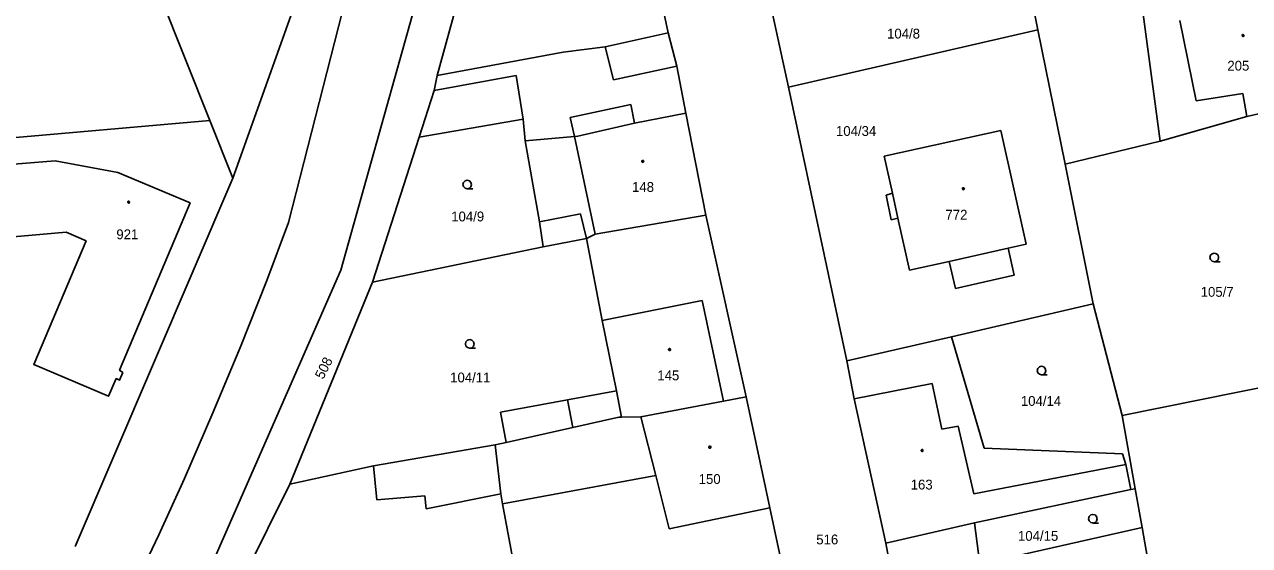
# Model space of a CAD drawing. Extents: x -757994 to -755874, y -1047691 to -1046119.
# Drawn here: x -756803.8 to -756698, y -1047019.3 to -1046974.3 of the extents above; entities that cross this region are included whole.
import ezdxf

# ---------------------------------------------------------------- set-up
doc = ezdxf.new("R2010")
doc.units = 0
doc.layers.add('katastrální mapa', color=7, linetype='Continuous')

msp = doc.modelspace()

# ---------------------------------------------------------------- linework, layer by layer
at = {"layer": 'katastrální mapa'}
for p, q in [((-756780.99, -1046991.44), (-756764.8, -1046928)), ((-756761.62, -1046942.65), (-756776.48, -1046995.54)), ((-756795.15, -1046964.07), (-756787.79, -1046982.63)), ((-756748.23, -1046975.07), (-756750.24, -1046965.33)), ((-756718.11, -1046965.95), (-756716.32, -1046974.79)), ((-756739.82, -1046970.56), (-756737.85, -1046979.76)), ((-756779.83, -1046970.85), (-756785.81, -1046987.62)), ((-756766.02, -1046970.94), (-756768.15, -1046978.75)), ((-756707.62, -1046970.57), (-756705.75, -1046984.42)), ((-756737.85, -1046979.76), (-756716.32, -1046974.79)), ((-756716.32, -1046974.79), (-756713.97, -1046986.4)), ((-756702.65, -1046980.93), (-756704.07, -1046974)), ((-756748.23, -1046975.07), (-756753.66, -1046976.28)), ((-756747.48, -1046977.94), (-756748.23, -1046975.07)), ((-756757.28, -1046976.74), (-756768.15, -1046978.75)), ((-756753.66, -1046976.28), (-756757.28, -1046976.74)), ((-756753.66, -1046976.28), (-756752.95, -1046979.13)), ((-756752.95, -1046979.13), (-756747.48, -1046977.94)), ((-756746.7, -1046982), (-756747.48, -1046977.94)), ((-756768.15, -1046978.75), (-756768.41, -1046980.03)), ((-756768.41, -1046980.03), (-756761.35, -1046978.75)), ((-756761.35, -1046978.75), (-756760.74, -1046982.5)), ((-756768.41, -1046980.03), (-756769.71, -1046984.06)), ((-756737.85, -1046979.76), (-756732.81, -1047003.38)), ((-756698.61, -1046980.3), (-756702.65, -1046980.93)), ((-756698.29, -1046982.28), (-756698.61, -1046980.3)), ((-756698.29, -1046982.28), (-756692.58, -1046980.95)), ((-756751.44, -1046981.26), (-756756.67, -1046982.36)), ((-756751.12, -1046982.87), (-756751.44, -1046981.26)), ((-756746.7, -1046982), (-756751.12, -1046982.87)), ((-756744.98, -1046990.79), (-756746.7, -1046982)), ((-756787.79, -1046982.63), (-756815.18, -1046985.04)), ((-756787.79, -1046982.63), (-756785.81, -1046987.62)), ((-756769.71, -1046984.06), (-756760.74, -1046982.5)), ((-756760.74, -1046982.5), (-756760.57, -1046984.38)), ((-756756.67, -1046982.36), (-756756.32, -1046984.02)), ((-756751.12, -1046982.87), (-756756.01, -1046983.99)), ((-756705.75, -1046984.42), (-756698.29, -1046982.28)), ((-756769.71, -1046984.06), (-756773.74, -1046996.58)), ((-756756.32, -1046984.02), (-756760.57, -1046984.38)), ((-756756.01, -1046983.99), (-756756.32, -1046984.02)), ((-756756.32, -1046984.02), (-756754.53, -1046992.45)), ((-756719.51, -1046983.48), (-756729.59, -1046985.71)), ((-756717.32, -1046993.32), (-756719.51, -1046983.48)), ((-756760.57, -1046984.38), (-756759.32, -1046991.39)), ((-756713.97, -1046986.4), (-756705.75, -1046984.42)), ((-756729.59, -1046985.71), (-756728.87, -1046988.91)), ((-756713.97, -1046986.4), (-756711.55, -1046998.45)), ((-756799.4, -1047019.41), (-756785.81, -1046987.62)), ((-756728.87, -1046988.91), (-756729.42, -1046989.07)), ((-756729.42, -1046989.07), (-756728.98, -1046991.2)), ((-756728.87, -1046988.91), (-756728.39, -1046991.07)), ((-756755.79, -1046990.69), (-756759.32, -1046991.39)), ((-756759.32, -1046991.39), (-756759.01, -1046993.53)), ((-756755.28, -1046992.81), (-756755.79, -1046990.69)), ((-756744.98, -1046990.79), (-756754.53, -1046992.45)), ((-756741.49, -1047006.49), (-756744.98, -1046990.79)), ((-756728.98, -1046991.2), (-756728.39, -1046991.07)), ((-756728.39, -1046991.07), (-756727.39, -1046995.56)), ((-756754.53, -1046992.45), (-756755.28, -1046992.81)), ((-756759.01, -1046993.53), (-756773.74, -1046996.58)), ((-756759.01, -1046993.53), (-756755.28, -1046992.81)), ((-756755.28, -1046992.81), (-756753.91, -1046999.9)), ((-756723.96, -1046994.8), (-756718.88, -1046993.66)), ((-756718.88, -1046993.66), (-756717.32, -1046993.32)), ((-756718.37, -1046995.98), (-756718.88, -1046993.66)), ((-756727.39, -1046995.56), (-756723.96, -1046994.8)), ((-756723.96, -1046994.8), (-756723.43, -1046997.14)), ((-756776.48, -1046995.54), (-756787.52, -1047020.76)), ((-756773.74, -1046996.58), (-756780.89, -1047014.02)), ((-756723.43, -1046997.14), (-756718.37, -1046995.98)), ((-756745.28, -1046998.17), (-756753.91, -1046999.9)), ((-756743.45, -1047006.86), (-756745.28, -1046998.17)), ((-756723.78, -1047001.31), (-756711.55, -1046998.45)), ((-756711.55, -1046998.45), (-756709.03, -1047008.1)), ((-756753.91, -1046999.9), (-756752.69, -1047005.97)), ((-756732.81, -1047003.38), (-756723.78, -1047001.31)), ((-756723.78, -1047001.31), (-756720.96, -1047010.91)), ((-756732.81, -1047003.38), (-756732.18, -1047006.66)), ((-756709.03, -1047008.1), (-756687.9, -1047003.85)), ((-756732.18, -1047006.66), (-756725.45, -1047005.34)), ((-756725.45, -1047005.34), (-756724.6, -1047009.29)), ((-756752.69, -1047005.97), (-756756.9, -1047006.74)), ((-756752.69, -1047005.97), (-756752.24, -1047008.24)), ((-756741.49, -1047006.49), (-756743.45, -1047006.86)), ((-756739.44, -1047016.08), (-756741.49, -1047006.49)), ((-756756.9, -1047006.74), (-756762.7, -1047007.8)), ((-756756.45, -1047009.13), (-756756.9, -1047006.74)), ((-756743.45, -1047006.86), (-756750.57, -1047008.22)), ((-756732.18, -1047006.66), (-756729.44, -1047019.12)), ((-756762.7, -1047007.8), (-756762.21, -1047010.42)), ((-756752.47, -1047008.24), (-756756.45, -1047009.13)), ((-756752.24, -1047008.24), (-756752.47, -1047008.24)), ((-756750.57, -1047008.22), (-756752.24, -1047008.24)), ((-756750.57, -1047008.22), (-756749.29, -1047013.29)), ((-756707.91, -1047014.42), (-756709.03, -1047008.1)), ((-756756.45, -1047009.13), (-756762.21, -1047010.42)), ((-756724.6, -1047009.29), (-756723.19, -1047009.01)), ((-756723.19, -1047009.01), (-756721.83, -1047014.85)), ((-756763.15, -1047010.63), (-756773.65, -1047012.46)), ((-756762.21, -1047010.42), (-756763.15, -1047010.63)), ((-756762.66, -1047014.85), (-756763.15, -1047010.63)), ((-756720.96, -1047010.91), (-756709.01, -1047011.4)), ((-756709.01, -1047011.4), (-756708.71, -1047012.33)), ((-756773.65, -1047012.46), (-756780.89, -1047014.02)), ((-756773.37, -1047015.39), (-756773.65, -1047012.46)), ((-756721.83, -1047014.85), (-756708.71, -1047012.33)), ((-756708.71, -1047012.33), (-756708.29, -1047014.5)), ((-756749.29, -1047013.29), (-756762.53, -1047015.73)), ((-756749.29, -1047013.29), (-756748.13, -1047017.89)), ((-756780.89, -1047014.02), (-756790.18, -1047032.81)), ((-756762.66, -1047014.85), (-756769.1, -1047016.15)), ((-756762.53, -1047015.73), (-756762.66, -1047014.85)), ((-756721.78, -1047017.37), (-756708.29, -1047014.5)), ((-756708.29, -1047014.5), (-756707.91, -1047014.42)), ((-756707.32, -1047017.76), (-756707.91, -1047014.42)), ((-756769.23, -1047015.03), (-756773.37, -1047015.39)), ((-756769.1, -1047016.15), (-756769.23, -1047015.03)), ((-756761.2, -1047022.76), (-756762.53, -1047015.73)), ((-756739.44, -1047016.08), (-756748.13, -1047017.89)), ((-756738.2, -1047021.87), (-756739.44, -1047016.08)), ((-756729.44, -1047019.12), (-756721.78, -1047017.37)), ((-756721.32, -1047020.94), (-756721.78, -1047017.37)), ((-756721.32, -1047020.94), (-756707.32, -1047017.76)), ((-756705.85, -1047026.09), (-756707.32, -1047017.76)), ((-756729.44, -1047019.12), (-756728.9, -1047021.94))]:
    msp.add_line(p, q, dxfattribs=at)
for points in [[(-756698.61, -1046975.21), (-756698.56, -1046975.22), (-756698.53, -1046975.26), (-756698.52, -1046975.29), (-756698.53, -1046975.34), (-756698.58, -1046975.37), (-756698.61, -1046975.38), (-756698.66, -1046975.36), (-756698.69, -1046975.33), (-756698.7, -1046975.29), (-756698.69, -1046975.25), (-756698.65, -1046975.21)], [(-756808.3, -1046986.7), (-756801.14, -1046986.11), (-756795.73, -1046987.12), (-756789.49, -1046989.74), (-756795.57, -1047004.2), (-756795.3, -1047004.39), (-756795.57, -1047005.04), (-756795.86, -1047004.91), (-756796.52, -1047006.44), (-756802.98, -1047003.7), (-756798.46, -1046993.02), (-756800.18, -1046992.27), (-756807.73, -1046992.92)], [(-756750.41, -1046986.07), (-756750.36, -1046986.08), (-756750.34, -1046986.12), (-756750.33, -1046986.15), (-756750.34, -1046986.2), (-756750.38, -1046986.23), (-756750.41, -1046986.24), (-756750.46, -1046986.22), (-756750.49, -1046986.19), (-756750.5, -1046986.15), (-756750.49, -1046986.11), (-756750.45, -1046986.07)], [(-756722.74, -1046988.43), (-756722.69, -1046988.44), (-756722.67, -1046988.48), (-756722.66, -1046988.51), (-756722.67, -1046988.55), (-756722.71, -1046988.59), (-756722.74, -1046988.6), (-756722.78, -1046988.58), (-756722.82, -1046988.55), (-756722.83, -1046988.51), (-756722.82, -1046988.47), (-756722.77, -1046988.43)], [(-756794.79, -1046989.6), (-756794.74, -1046989.61), (-756794.72, -1046989.65), (-756794.71, -1046989.68), (-756794.72, -1046989.73), (-756794.76, -1046989.76), (-756794.79, -1046989.77), (-756794.84, -1046989.75), (-756794.86, -1046989.72), (-756794.88, -1046989.68), (-756794.86, -1046989.64), (-756794.83, -1046989.6)], [(-756748.11, -1047002.32), (-756748.06, -1047002.33), (-756748.03, -1047002.37), (-756748.02, -1047002.4), (-756748.03, -1047002.45), (-756748.08, -1047002.48), (-756748.11, -1047002.49), (-756748.16, -1047002.47), (-756748.19, -1047002.44), (-756748.2, -1047002.4), (-756748.19, -1047002.36), (-756748.15, -1047002.32)], [(-756744.62, -1047010.75), (-756744.57, -1047010.76), (-756744.54, -1047010.81), (-756744.53, -1047010.84), (-756744.54, -1047010.89), (-756744.59, -1047010.92), (-756744.62, -1047010.93), (-756744.67, -1047010.91), (-756744.7, -1047010.88), (-756744.71, -1047010.84), (-756744.7, -1047010.79), (-756744.66, -1047010.76)], [(-756726.3, -1047011.03), (-756726.25, -1047011.04), (-756726.23, -1047011.09), (-756726.22, -1047011.12), (-756726.23, -1047011.17), (-756726.27, -1047011.2), (-756726.3, -1047011.21), (-756726.35, -1047011.19), (-756726.38, -1047011.16), (-756726.39, -1047011.12), (-756726.38, -1047011.08), (-756726.34, -1047011.04)]]:
    msp.add_lwpolyline(points, close=True, dxfattribs=at)
for points in [[(-756765.56, -1046988.52), (-756765.75, -1046988.47), (-756765.89, -1046988.34), (-756765.94, -1046988.15), (-756765.89, -1046987.97), (-756765.75, -1046987.83), (-756765.57, -1046987.78), (-756765.38, -1046987.83), (-756765.25, -1046987.97), (-756765.2, -1046988.16), (-756765.25, -1046988.35), (-756765.38, -1046988.48), (-756765.57, -1046988.53), (-756765.07, -1046988.53)], [(-756836.87, -1047091.03), (-756833.57, -1047086.8), (-756829.82, -1047081.82), (-756826.16, -1047076.78), (-756822.58, -1047071.68), (-756819.1, -1047066.52), (-756815.7, -1047061.3), (-756812.39, -1047056.03), (-756809.17, -1047050.69), (-756806.05, -1047045.31), (-756803.01, -1047039.87), (-756800.07, -1047034.38), (-756797.23, -1047028.84), (-756794.48, -1047023.25), (-756792.19, -1047018.39), (-756789.97, -1047013.53), (-756787.51, -1047007.87), (-756785.14, -1047002.18), (-756782.87, -1046996.44), (-756780.99, -1046991.44)], [(-756701.08, -1046994.82), (-756701.27, -1046994.77), (-756701.41, -1046994.64), (-756701.46, -1046994.45), (-756701.41, -1046994.26), (-756701.27, -1046994.13), (-756701.09, -1046994.08), (-756700.9, -1046994.13), (-756700.76, -1046994.26), (-756700.72, -1046994.46), (-756700.76, -1046994.65), (-756700.9, -1046994.78), (-756701.09, -1046994.83), (-756700.59, -1046994.83)], [(-756765.35, -1047002.29), (-756765.54, -1047002.24), (-756765.68, -1047002.11), (-756765.73, -1047001.92), (-756765.68, -1047001.74), (-756765.54, -1047001.6), (-756765.35, -1047001.55), (-756765.17, -1047001.6), (-756765.03, -1047001.74), (-756764.98, -1047001.93), (-756765.03, -1047002.12), (-756765.17, -1047002.25), (-756765.36, -1047002.3), (-756764.86, -1047002.3)], [(-756715.99, -1047004.59), (-756716.18, -1047004.54), (-756716.32, -1047004.41), (-756716.36, -1047004.22), (-756716.32, -1047004.03), (-756716.18, -1047003.9), (-756715.99, -1047003.85), (-756715.81, -1047003.9), (-756715.68, -1047004.03), (-756715.62, -1047004.23), (-756715.68, -1047004.42), (-756715.81, -1047004.55), (-756716, -1047004.6), (-756715.5, -1047004.6)], [(-756711.56, -1047017.38), (-756711.75, -1047017.33), (-756711.89, -1047017.2), (-756711.94, -1047017.01), (-756711.89, -1047016.83), (-756711.75, -1047016.69), (-756711.57, -1047016.64), (-756711.38, -1047016.69), (-756711.25, -1047016.83), (-756711.2, -1047017.02), (-756711.25, -1047017.21), (-756711.38, -1047017.34), (-756711.57, -1047017.39), (-756711.07, -1047017.39)]]:
    msp.add_lwpolyline(points, dxfattribs=at)

# ---------------------------------------------------------------- texts
for s, p in [('104/8', (-756729.33, -1046975.55)), ('205', (-756699.96, -1046978.32)), ('104/34', (-756733.74, -1046983.96)), ('148', (-756751.34, -1046988.79)), ('104/9', (-756766.95, -1046991.34)), ('772', (-756724.29, -1046991.19)), ('921', (-756795.85, -1046992.88)), ('105/7', (-756702.26, -1046997.85)), ('104/11', (-756767.04, -1047005.24)), ('145', (-756749.16, -1047005.06)), ('104/14', (-756717.78, -1047007.27)), ('150', (-756745.59, -1047014.01)), ('163', (-756727.29, -1047014.49)), ('104/15', (-756718.03, -1047018.92)), ('516', (-756735.44, -1047019.23))]:
    msp.add_text(s, height=0.85, dxfattribs=at).set_placement(p)
msp.add_text('508', height=0.85, rotation=63.4264, dxfattribs=at).set_placement((-756778, -1047005.03))

doc.saveas('drawing.dxf')
